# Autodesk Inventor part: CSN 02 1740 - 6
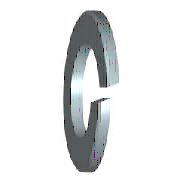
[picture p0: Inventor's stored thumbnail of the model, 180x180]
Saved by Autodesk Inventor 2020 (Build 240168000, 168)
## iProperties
Created: 2019-01
Part Number: CSN 02 1740 - 6
Material: Ocel, měkká
Description: Pružné podložky čtvercového průřezu
Document SubType Name: Modeling
Standard: CSN 02 1740
Designer: doma
Standards Organization: CSN
Language: cs-CZ
Size Designation: 6
Categories: <MemberInstance><Categories><Category DisplayName="Spojovací materiál" InternalName="e4da775c-781d-43d5-af7c-5136215cf5a6" Mnemonic="FSTN"><Category DisplayName
Density: 7.85 g/cm^3
Appearance: Pololeštěná
Mass: 0.411094 g
Surface Area: 1.44237 cm^2
Volume: 0.0523686 cm^3
IsCustomPart: 0
Author: doma
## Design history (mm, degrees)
sketch "Náčrt1"
  geometry: C1 r 4.55 at (0, 0); C2 r 3.05 at (0, 0); 1 further point
  constraints: 2 centre point, 2 coincident
  dimensions: "d0" = 6.1 diameter of C2 (= SD1); "d1" = 9.1 diameter of C1 (= SD2)
extrude "Těleso" new body sketch "Náčrt1" distance "d2" = 1.5 (= SD); taper "d3" = 0 deg
sketch "Náčrt2"
  geometry: L1 (0, -3.05)-(0, 3.05) reference; L2 (1.5, 4.55)-(1.5, -4.55) reference; L3 (-1.2, 0)-(7.2, 0) reference; L4 (0, -0.3)-(1.5, -0.036); L5 (0, 0.3)-(1.5, 0.564)
  constraints: 4 end point, 4 point on line, 1 parallel
  dimensions: "d4" = 0.3 distance from line of L3 L4.start (= 0.2 x SD); "d5" = 0.3 distance from line of L3 L5.start (= 0.2 x SD); "d6" = 80 deg angle of L2 L4 (= FAWI)
extrude "Výřez" cut sketch "Náčrt2" stored distance "d7" = 1.5 (= SD); taper "d8" = 0 deg
workaxis "Work Axis1"
workplane "Work Plane1"
body "Solid1"
other parameters: "SD1" = 6.1 [user parameter; used in 1 equation term], "SD2" = 9.1 [user parameter; used in 1 equation term], "SD" = 1.5 [user parameter; used in 4 equation terms], "FAWI" = 80 deg [user parameter; used in 1 equation term], "d9" = 0, "d10" = 0, "d11" = 0, "d12" = 0, "NND" = 6 [user parameter]
